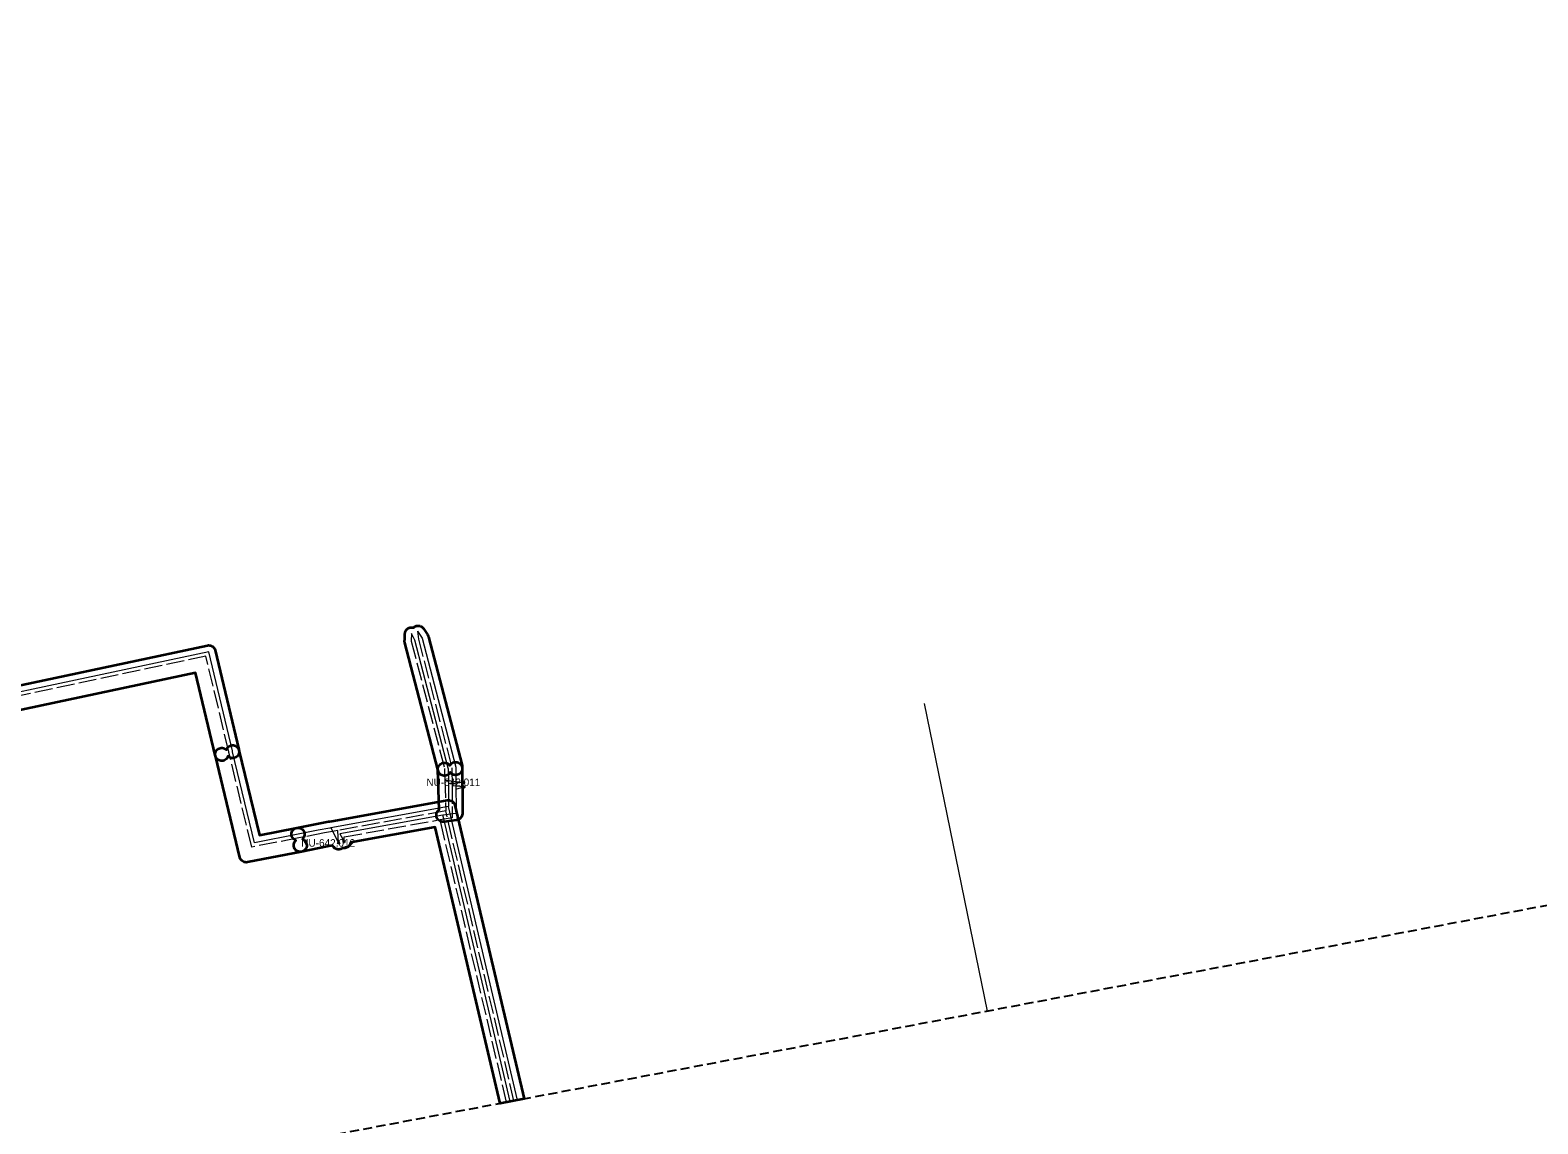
# Model space of a CAD drawing. Extents: x -452602 to -451136, y -1100088 to -1099653.
# Drawn here: x -452078.2 to -451916.9, y -1099987.5 to -1099870.6 of the extents above; entities that cross this region are included whole.
import ezdxf

# ---------------------------------------------------------------- set-up
doc = ezdxf.new("R2010")
doc.units = 0
doc.header["$LTSCALE"] = 0.32
doc.header["$PDMODE"] = 32
doc.header["$PDSIZE"] = 0.16
doc.linetypes.add('LONG_DASHED', pattern=[7.5, 6, -1.5])
doc.linetypes.add('MEDIUM_DASHED', pattern=[4.5, 3, -1.5])
for name, color, linetype, lineweight in [('2', 7, 'Continuous', 13), ('62', 7, 'MEDIUM_DASHED', 25), ('8', 7, 'Continuous', 35)]:
    doc.layers.add(name, color=color, linetype=linetype, lineweight=lineweight)
doc.layers.add('4', color=7, linetype='Continuous')

msp = doc.modelspace()

# ---------------------------------------------------------------- linework, layer by layer
at = {"layer": '2'}
for p, q in [((-451982.534, -1099942.573), (-451975.776, -1099975.486)), ((-452033.457, -1099949.524), (-452033.443, -1099951.112)), ((-452032.657, -1099949.524), (-452032.637, -1099951.721)), ((-452033.443, -1099951.112), (-452031.79, -1099950.989)), ((-452033.443, -1099951.112), (-452033.42, -1099953.596)), ((-452032.637, -1099951.721), (-452031.788, -1099951.495)), ((-452033.42, -1099953.596), (-452046.003, -1099955.863)), ((-452026.029, -1099984.989), (-452033.42, -1099953.596)), ((-452034.026, -1099954.518), (-452045.045, -1099956.503)), ((-452046.003, -1099955.863), (-452045.183, -1099957.475)), ((-452045.045, -1099956.503), (-452044.595, -1099957.336))]:
    msp.add_line(p, q, dxfattribs=at)
at = {"layer": '2', "linetype": 'LONG_DASHED'}
for p, q in [((-452033.858, -1099949.602), (-452033.823, -1099950.749)), ((-452033.823, -1099950.749), (-452033.722, -1099954.057)), ((-452033.823, -1099950.749), (-452031.79, -1099950.989)), ((-452033.057, -1099949.524), (-452033.04, -1099951.388)), ((-452031.788, -1099951.495), (-452033.04, -1099951.388)), ((-452033.722, -1099954.057), (-452045.277, -1099956.138)), ((-452026.423, -1099985.064), (-452033.722, -1099954.057)), ((-452045.183, -1099957.475), (-452045.277, -1099956.138)), ((-452044.595, -1099957.336), (-452044.595, -1099956.828))]:
    msp.add_line(p, q, dxfattribs=at)
for points in [[(-452037.381, -1099935.089), (-452037.418, -1099935.886), (-452033.859, -1099949.535), (-452033.858, -1099949.602)], [(-452036.725, -1099934.846), (-452036.644, -1099935.685), (-452033.057, -1099949.44), (-452033.057, -1099949.524)], [(-452056.916, -1099947.815), (-452056.936, -1099947.728), (-452059.373, -1099937.511), (-452084.557, -1099942.854)], [(-452049.442, -1099956.94), (-452054.475, -1099957.923), (-452056.916, -1099947.815)], [(-452033.04, -1099951.388), (-452033.02, -1099953.592), (-452033.026, -1099954.777), (-452034.314, -1099954.99)], [(-452044.595, -1099956.828), (-452034.661, -1099955.049), (-452034.314, -1099954.99)], [(-452027.21, -1099985.212), (-452034.263, -1099955.251), (-452034.314, -1099954.99)], [(-452045.277, -1099956.138), (-452046.043, -1099956.276), (-452046.7, -1099956.405), (-452049.442, -1099956.94)]]:
    msp.add_lwpolyline(points, dxfattribs=at)
at = {"layer": '2'}
for points in [[(-452033.457, -1099949.524), (-452033.457, -1099949.491), (-452037.031, -1099935.785), (-452037.381, -1099935.089)], [(-452036.725, -1099934.846), (-452036.257, -1099935.584), (-452032.657, -1099949.389), (-452032.657, -1099949.524)], [(-452056.527, -1099947.721), (-452056.548, -1099947.635), (-452059.074, -1099937.039), (-452085.3, -1099942.603)], [(-452049.527, -1099956.548), (-452054.175, -1099957.456), (-452056.527, -1099947.721)], [(-452032.637, -1099951.721), (-452032.619, -1099953.588), (-452032.645, -1099954.338), (-452034.026, -1099954.518)], [(-452026.817, -1099985.138), (-452033.931, -1099954.918), (-452034.026, -1099954.518)], [(-452046.003, -1099955.863), (-452046.118, -1099955.883), (-452047.38, -1099956.13), (-452049.527, -1099956.548)]]:
    msp.add_lwpolyline(points, dxfattribs=at)
at = {"layer": '4'}
for p in [(-452031.79, -1099950.989), (-452031.788, -1099951.495), (-452044.595, -1099957.336), (-452045.183, -1099957.475)]:
    msp.add_point(p, dxfattribs=at)
at = {"layer": '62'}
msp.add_lwpolyline([(-451137.485, -1099816.961), (-452572.169, -1100088.267), (-452602.314, -1099919.678), (-451137.485, -1099652.838), (-451136.368, -1099701.963)], close=True, dxfattribs=at)
at = {"layer": '8'}
for points in [[(-452036.19, -1099934.452), (-452036.159, -1099934.486), (-452036.13, -1099934.521), (-452036.104, -1099934.557), (-452035.679, -1099935.189), (-452035.676, -1099935.194), (-452035.63, -1099935.274), (-452035.594, -1099935.359), (-452035.58, -1099935.407), (-452035.57, -1099935.447), (-452031.98, -1099949.212), (-452031.963, -1099949.3), (-452031.957, -1099949.388), (-452031.957, -1099949.524), (-452031.967, -1099949.64), (-452031.995, -1099949.752), (-452032.042, -1099949.858), (-452032.105, -1099949.955), (-452032.184, -1099950.04), (-452032.276, -1099950.111), (-452032.377, -1099950.166), (-452032.487, -1099950.204), (-452032.601, -1099950.222), (-452032.706, -1099950.223), (-452032.81, -1099950.208), (-452032.91, -1099950.177), (-452033.005, -1099950.132), (-452033.092, -1099950.073), (-452033.169, -1099950.002), (-452033.234, -1099949.921), (-452033.297, -1099950.021), (-452033.376, -1099950.11), (-452033.469, -1099950.184), (-452033.573, -1099950.241), (-452033.685, -1099950.28), (-452033.802, -1099950.299), (-452033.913, -1099950.299), (-452034.024, -1099950.282), (-452034.13, -1099950.246), (-452034.229, -1099950.195), (-452034.319, -1099950.128), (-452034.397, -1099950.048), (-452034.461, -1099949.956), (-452034.51, -1099949.855), (-452034.542, -1099949.748), (-452034.557, -1099949.637), (-452038.095, -1099936.068), (-452038.096, -1099936.063), (-452038.11, -1099935.998), (-452038.118, -1099935.932), (-452038.12, -1099935.861), (-452038.115, -1099935.789), (-452038.086, -1099935.1), (-452038.085, -1099935.084), (-452038.08, -1099935.039), (-452038.073, -1099934.993), (-452038.062, -1099934.949), (-452038.049, -1099934.905), (-452038.033, -1099934.862), (-452038.014, -1099934.82), (-452037.993, -1099934.78), (-452037.968, -1099934.741), (-452037.942, -1099934.704), (-452037.913, -1099934.668), (-452037.881, -1099934.635), (-452037.848, -1099934.604), (-452037.812, -1099934.575), (-452037.775, -1099934.548), (-452037.736, -1099934.524), (-452037.696, -1099934.502), (-452037.654, -1099934.483), (-452037.611, -1099934.467), (-452037.568, -1099934.454), (-452037.523, -1099934.443), (-452037.478, -1099934.436), (-452037.432, -1099934.432), (-452037.386, -1099934.43), (-452037.34, -1099934.432), (-452037.295, -1099934.436), (-452037.25, -1099934.443), (-452037.205, -1099934.454), (-452037.187, -1099934.459), (-452037.18, -1099934.452), (-452037.147, -1099934.421), (-452037.111, -1099934.392), (-452037.074, -1099934.365), (-452037.035, -1099934.341), (-452036.995, -1099934.32), (-452036.953, -1099934.301), (-452036.91, -1099934.285), (-452036.866, -1099934.271), (-452036.822, -1099934.261), (-452036.777, -1099934.253), (-452036.731, -1099934.249), (-452036.685, -1099934.247), (-452036.639, -1099934.249), (-452036.594, -1099934.253), (-452036.549, -1099934.261), (-452036.504, -1099934.271), (-452036.46, -1099934.285)], [(-452036.417, -1099934.301), (-452036.376, -1099934.32), (-452036.335, -1099934.341), (-452036.296, -1099934.365), (-452036.259, -1099934.392), (-452036.224, -1099934.421), (-452036.19, -1099934.452)], [(-452085.445, -1099941.918), (-452059.219, -1099936.354), (-452059.1, -1099936.339), (-452058.98, -1099936.345), (-452058.862, -1099936.371), (-452058.751, -1099936.417), (-452058.65, -1099936.481), (-452058.561, -1099936.562), (-452058.487, -1099936.656), (-452058.43, -1099936.762), (-452058.393, -1099936.876)], [(-452058.393, -1099936.876), (-452055.867, -1099947.47), (-452055.847, -1099947.554), (-452055.829, -1099947.674), (-452055.832, -1099947.795), (-452055.855, -1099947.914), (-452055.899, -1099948.026), (-452055.962, -1099948.13), (-452056.041, -1099948.221), (-452056.135, -1099948.297), (-452056.241, -1099948.356), (-452056.355, -1099948.396), (-452056.475, -1099948.415), (-452056.596, -1099948.414), (-452056.715, -1099948.392), (-452056.828, -1099948.35), (-452056.932, -1099948.288), (-452057.025, -1099948.21), (-452057.071, -1099948.322), (-452057.135, -1099948.425), (-452057.217, -1099948.515), (-452057.312, -1099948.59), (-452057.419, -1099948.647), (-452057.535, -1099948.684), (-452057.655, -1099948.701), (-452057.776, -1099948.697), (-452057.895, -1099948.673), (-452058.008, -1099948.628), (-452058.111, -1099948.564), (-452058.202, -1099948.483), (-452058.277, -1099948.388), (-452058.335, -1099948.282), (-452058.374, -1099948.166), (-452058.395, -1099948.079), (-452060.492, -1099939.282), (-452083.172, -1099944.094)], [(-452032.738, -1099953.435), (-452025.341, -1099984.859), (-452027.899, -1099985.343), (-452034.854, -1099955.795), (-452043.899, -1099957.415), (-452043.901, -1099957.427), (-452043.908, -1099957.472), (-452043.918, -1099957.517), (-452043.932, -1099957.561), (-452043.948, -1099957.603), (-452043.967, -1099957.645), (-452043.988, -1099957.686), (-452044.013, -1099957.725), (-452044.039, -1099957.762), (-452044.068, -1099957.797), (-452044.1, -1099957.831), (-452044.133, -1099957.862), (-452044.168, -1099957.891), (-452044.206, -1099957.918), (-452044.245, -1099957.942), (-452044.285, -1099957.963), (-452044.327, -1099957.982), (-452044.37, -1099957.999), (-452044.413, -1099958.012), (-452044.458, -1099958.022), (-452044.503, -1099958.03), (-452044.549, -1099958.034), (-452044.595, -1099958.036), (-452044.64, -1099958.034), (-452044.686, -1099958.03), (-452044.731, -1099958.022), (-452044.743, -1099958.019), (-452044.757, -1099958.031), (-452044.794, -1099958.057), (-452044.833, -1099958.082), (-452044.873, -1099958.103), (-452044.915, -1099958.122), (-452044.958, -1099958.138), (-452045.002, -1099958.151), (-452045.046, -1099958.162), (-452045.092, -1099958.169), (-452045.137, -1099958.174), (-452045.183, -1099958.175), (-452045.229, -1099958.174), (-452045.274, -1099958.169), (-452045.32, -1099958.162), (-452045.364, -1099958.151), (-452045.408, -1099958.138), (-452045.451, -1099958.122), (-452045.493, -1099958.103), (-452045.533, -1099958.082), (-452045.572, -1099958.057), (-452045.609, -1099958.031), (-452045.644, -1099958.002), (-452045.678, -1099957.97), (-452045.709, -1099957.937), (-452045.738, -1099957.901), (-452045.765, -1099957.864), (-452045.789, -1099957.825), (-452045.807, -1099957.793), (-452045.823, -1099957.762), (-452046.413, -1099957.877), (-452049.156, -1099958.412), (-452049.232, -1099958.423), (-452049.348, -1099958.422), (-452049.462, -1099958.403), (-452049.571, -1099958.365), (-452049.673, -1099958.31), (-452049.763, -1099958.238), (-452049.842, -1099958.153), (-452049.905, -1099958.056), (-452049.951, -1099957.95), (-452049.979, -1099957.838), (-452049.988, -1099957.723), (-452049.978, -1099957.608), (-452049.95, -1099957.496), (-452049.903, -1099957.39), (-452049.839, -1099957.293), (-452049.761, -1099957.208), (-452049.872, -1099957.158), (-452049.972, -1099957.089), (-452050.059, -1099957.004), (-452050.13, -1099956.905), (-452050.182, -1099956.796), (-452050.215, -1099956.679), (-452050.227, -1099956.557), (-452050.218, -1099956.436), (-452050.188, -1099956.318), (-452050.138, -1099956.207), (-452050.07, -1099956.107), (-452049.985, -1099956.019), (-452049.887, -1099955.948), (-452049.777, -1099955.895), (-452049.66, -1099955.861), (-452047.514, -1099955.443), (-452046.251, -1099955.197), (-452046.242, -1099955.195), (-452046.139, -1099955.176), (-452046.127, -1099955.174), (-452046.121, -1099955.173)], [(-452046.095, -1099955.168), (-452033.551, -1099952.908), (-452033.544, -1099952.907), (-452033.457, -1099952.897), (-452033.37, -1099952.898), (-452033.284, -1099952.91), (-452033.233, -1099952.922), (-452033.133, -1099952.958), (-452033.039, -1099953.009), (-452032.954, -1099953.074), (-452032.88, -1099953.15), (-452032.818, -1099953.238), (-452032.771, -1099953.333), (-452032.738, -1099953.435)]]:
    msp.add_lwpolyline(points, dxfattribs=at)
for points in [[(-452055.846, -1099947.556), (-452053.652, -1099956.641), (-452049.661, -1099955.861), (-452049.541, -1099955.85), (-452049.42, -1099955.858), (-452049.303, -1099955.887), (-452049.193, -1099955.936), (-452049.093, -1099956.003), (-452049.006, -1099956.087), (-452048.934, -1099956.184), (-452048.88, -1099956.291), (-452048.846, -1099956.407), (-452048.831, -1099956.527), (-452048.838, -1099956.647), (-452048.865, -1099956.765), (-452048.912, -1099956.876), (-452048.977, -1099956.977), (-452049.059, -1099957.066), (-452048.948, -1099957.116), (-452048.848, -1099957.185), (-452048.762, -1099957.269), (-452048.691, -1099957.368), (-452048.638, -1099957.477), (-452048.605, -1099957.594), (-452048.593, -1099957.714), (-452048.601, -1099957.835), (-452048.631, -1099957.953), (-452048.68, -1099958.064), (-452048.747, -1099958.164), (-452048.831, -1099958.252), (-452048.929, -1099958.324), (-452049.038, -1099958.377), (-452049.154, -1099958.412), (-452054.941, -1099959.542), (-452055.058, -1099959.554), (-452055.176, -1099959.547), (-452055.292, -1099959.519), (-452055.4, -1099959.473), (-452055.5, -1099959.409), (-452055.587, -1099959.329), (-452055.66, -1099959.235), (-452055.715, -1099959.131), (-452055.753, -1099959.019), (-452058.373, -1099948.167), (-452058.39, -1099948.047), (-452058.386, -1099947.927), (-452058.362, -1099947.808), (-452058.317, -1099947.696), (-452058.254, -1099947.593), (-452058.174, -1099947.503), (-452058.08, -1099947.428), (-452057.974, -1099947.37), (-452057.86, -1099947.331), (-452057.74, -1099947.312), (-452057.62, -1099947.314), (-452057.501, -1099947.336), (-452057.388, -1099947.379), (-452057.284, -1099947.44), (-452057.193, -1099947.519), (-452057.147, -1099947.407), (-452057.082, -1099947.305), (-452057.001, -1099947.215), (-452056.906, -1099947.141), (-452056.8, -1099947.084), (-452056.685, -1099947.047), (-452056.566, -1099947.029), (-452056.445, -1099947.033), (-452056.327, -1099947.057), (-452056.214, -1099947.101), (-452056.111, -1099947.163), (-452056.02, -1099947.243), (-452055.944, -1099947.337), (-452055.886, -1099947.442)], [(-452031.957, -1099949.518), (-452031.92, -1099953.582), (-452031.92, -1099953.588), (-452031.92, -1099953.612), (-452031.945, -1099954.361), (-452031.958, -1099954.47), (-452031.987, -1099954.576), (-452032.032, -1099954.675), (-452032.092, -1099954.766), (-452032.165, -1099954.847), (-452032.251, -1099954.916), (-452032.345, -1099954.97), (-452032.447, -1099955.009), (-452032.554, -1099955.032), (-452033.936, -1099955.212), (-452033.971, -1099955.215), (-452034.093, -1099955.215), (-452034.212, -1099955.193), (-452034.327, -1099955.151), (-452034.432, -1099955.089), (-452034.525, -1099955.01), (-452034.603, -1099954.916), (-452034.664, -1099954.81), (-452034.705, -1099954.695), (-452034.725, -1099954.575), (-452034.725, -1099954.453), (-452034.703, -1099954.333), (-452034.661, -1099954.219), (-452034.599, -1099954.113), (-452034.52, -1099954.02), (-452034.426, -1099953.942), (-452034.557, -1099949.623), (-452034.551, -1099949.503), (-452034.524, -1099949.386), (-452034.477, -1099949.276), (-452034.413, -1099949.175), (-452034.332, -1099949.087), (-452034.237, -1099949.013), (-452034.131, -1099948.957), (-452034.017, -1099948.92), (-452033.899, -1099948.903), (-452033.779, -1099948.906), (-452033.662, -1099948.929), (-452033.55, -1099948.973), (-452033.447, -1099949.034), (-452033.356, -1099949.113), (-452033.28, -1099949.205), (-452033.219, -1099949.107), (-452033.142, -1099949.019), (-452033.052, -1099948.946), (-452032.951, -1099948.889), (-452032.842, -1099948.849), (-452032.728, -1099948.828), (-452032.611, -1099948.826), (-452032.496, -1099948.843), (-452032.386, -1099948.879), (-452032.283, -1099948.933), (-452032.19, -1099949.003), (-452032.111, -1099949.088), (-452032.046, -1099949.184), (-452031.998, -1099949.29), (-452031.968, -1099949.402)]]:
    msp.add_lwpolyline(points, close=True, dxfattribs=at)

# ---------------------------------------------------------------- texts
at = {"layer": '4'}
for s, p in [('NU-642.011', (-452035.79, -1099951.389)), ('NU-642.012', (-452049.183, -1099957.875))]:
    msp.add_text(s, height=0.8, dxfattribs=at).set_placement(p)

doc.saveas('drawing.dxf')
